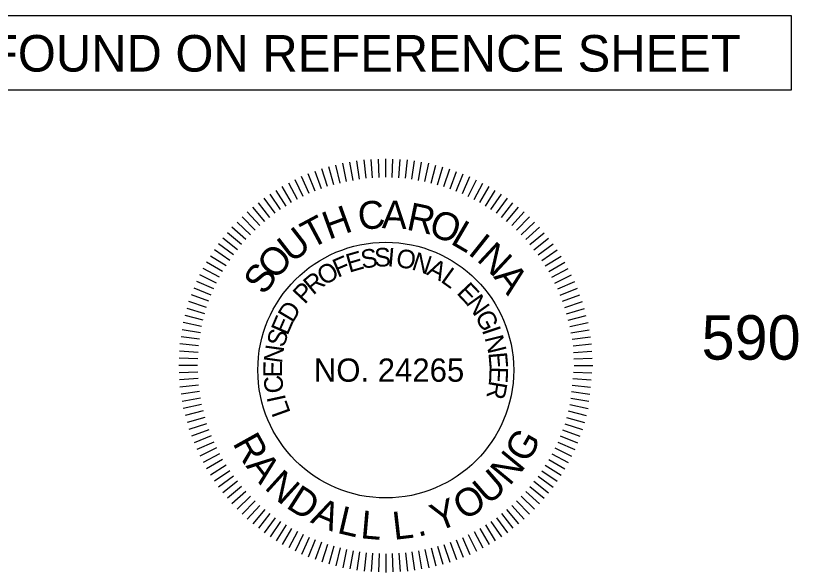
# Model space of a CAD drawing. Extents: x 1964377 to 1966966, y 1116414 to 1123213.
# Drawn here: x 1966800.1 to 1966949.9, y 1117986.1 to 1118092.7 of the extents above; entities that cross this region are included whole.
import ezdxf

# ---------------------------------------------------------------- set-up
doc = ezdxf.new("R2010")
doc.units = 0
for name, color, linetype in [('RD_DDB_Profile_Elev', 7, 'Continuous'), ('RD_Sketch1', 7, 'Continuous'), ('RD_TX_PEShield', 7, 'Continuous')]:
    doc.layers.add(name, color=color, linetype=linetype)

msp = doc.modelspace()

# ---------------------------------------------------------------- linework, layer by layer
at = {"layer": 'RD_Sketch1'}
msp.add_lwpolyline([(1966648.09, 1118092.67), (1966948.51, 1118092.67), (1966948.51, 1118078.41), (1966648.09, 1118078.41)], close=True, dxfattribs=at)
at = {"layer": 'RD_TX_PEShield'}
for p, q in [((1966865.89, 1118061.33), (1966865.39, 1118064.85)), ((1966865.89, 1118061.33), (1966865.39, 1118064.85)), ((1966867.13, 1118061.52), (1966866.76, 1118065.06)), ((1966867.13, 1118061.52), (1966866.76, 1118065.06)), ((1966868.39, 1118061.59), (1966868.14, 1118065.14)), ((1966868.39, 1118061.59), (1966868.14, 1118065.14)), ((1966869.64, 1118061.65), (1966869.52, 1118065.21)), ((1966869.64, 1118061.65), (1966869.52, 1118065.21)), ((1966870.9, 1118061.72), (1966870.9, 1118065.28)), ((1966870.9, 1118061.72), (1966870.9, 1118065.28)), ((1966872.15, 1118061.65), (1966872.28, 1118065.21)), ((1966872.15, 1118061.65), (1966872.28, 1118065.21)), ((1966873.41, 1118061.59), (1966873.66, 1118065.14)), ((1966873.41, 1118061.59), (1966873.66, 1118065.14)), ((1966874.67, 1118061.52), (1966875.04, 1118065.06)), ((1966874.67, 1118061.52), (1966875.04, 1118065.06)), ((1966875.91, 1118061.33), (1966876.4, 1118064.85)), ((1966875.91, 1118061.33), (1966876.4, 1118064.85)), ((1966859.76, 1118059.96), (1966858.66, 1118063.34)), ((1966859.76, 1118059.96), (1966858.66, 1118063.34)), ((1966860.98, 1118060.28), (1966860, 1118063.7)), ((1966860.98, 1118060.28), (1966860, 1118063.7)), ((1966862.19, 1118060.61), (1966861.33, 1118064.06)), ((1966862.19, 1118060.61), (1966861.33, 1118064.06)), ((1966863.4, 1118060.93), (1966862.66, 1118064.41)), ((1966863.4, 1118060.93), (1966862.66, 1118064.41)), ((1966864.65, 1118061.13), (1966864.03, 1118064.63)), ((1966864.65, 1118061.13), (1966864.03, 1118064.63)), ((1966877.15, 1118061.13), (1966877.77, 1118064.63)), ((1966877.15, 1118061.13), (1966877.77, 1118064.63)), ((1966878.39, 1118060.93), (1966879.13, 1118064.41)), ((1966878.39, 1118060.93), (1966879.13, 1118064.41)), ((1966878.39, 1118060.93), (1966879.13, 1118064.41)), ((1966879.61, 1118060.61), (1966880.47, 1118064.06)), ((1966879.61, 1118060.61), (1966880.47, 1118064.06)), ((1966879.61, 1118060.61), (1966880.47, 1118064.06)), ((1966880.82, 1118060.28), (1966881.8, 1118063.7)), ((1966880.82, 1118060.28), (1966881.8, 1118063.7)), ((1966880.82, 1118060.28), (1966881.8, 1118063.7)), ((1966882.04, 1118059.96), (1966883.14, 1118063.34)), ((1966882.04, 1118059.96), (1966883.14, 1118063.34)), ((1966882.04, 1118059.96), (1966883.14, 1118063.34)), ((1966856.24, 1118058.6), (1966854.79, 1118061.86)), ((1966856.24, 1118058.6), (1966854.79, 1118061.86)), ((1966857.41, 1118059.06), (1966856.08, 1118062.35)), ((1966857.41, 1118059.06), (1966856.08, 1118062.35)), ((1966858.59, 1118059.51), (1966857.37, 1118062.85)), ((1966858.59, 1118059.51), (1966857.37, 1118062.85)), ((1966883.21, 1118059.51), (1966884.43, 1118062.85)), ((1966883.21, 1118059.51), (1966884.43, 1118062.85)), ((1966883.21, 1118059.51), (1966884.43, 1118062.85)), ((1966884.38, 1118059.06), (1966885.72, 1118062.35)), ((1966884.38, 1118059.06), (1966885.72, 1118062.35)), ((1966884.38, 1118059.06), (1966885.72, 1118062.35)), ((1966885.56, 1118058.6), (1966887.01, 1118061.86)), ((1966885.56, 1118058.6), (1966887.01, 1118061.86)), ((1966885.56, 1118058.6), (1966887.01, 1118061.86)), ((1966854, 1118057.46), (1966852.33, 1118060.6)), ((1966854, 1118057.46), (1966852.33, 1118060.6)), ((1966855.12, 1118058.03), (1966853.56, 1118061.23)), ((1966855.12, 1118058.03), (1966853.56, 1118061.23)), ((1966886.68, 1118058.03), (1966888.24, 1118061.23)), ((1966886.68, 1118058.03), (1966888.24, 1118061.23)), ((1966886.68, 1118058.03), (1966888.24, 1118061.23)), ((1966887.8, 1118057.46), (1966889.47, 1118060.6)), ((1966887.8, 1118057.46), (1966889.47, 1118060.6)), ((1966887.8, 1118057.46), (1966889.47, 1118060.6)), ((1966851.82, 1118056.21), (1966849.94, 1118059.22)), ((1966851.82, 1118056.21), (1966849.94, 1118059.22)), ((1966852.88, 1118056.89), (1966851.1, 1118059.97)), ((1966852.88, 1118056.89), (1966851.1, 1118059.97)), ((1966888.92, 1118056.89), (1966890.7, 1118059.97)), ((1966888.92, 1118056.89), (1966890.7, 1118059.97)), ((1966888.92, 1118056.89), (1966890.7, 1118059.97)), ((1966889.98, 1118056.21), (1966891.86, 1118059.22)), ((1966889.98, 1118056.21), (1966891.86, 1118059.22)), ((1966889.98, 1118056.21), (1966891.86, 1118059.22)), ((1966849.71, 1118054.84), (1966847.62, 1118057.72)), ((1966849.71, 1118054.84), (1966847.62, 1118057.72)), ((1966850.77, 1118055.52), (1966848.78, 1118058.47)), ((1966850.77, 1118055.52), (1966848.78, 1118058.47)), ((1966891.03, 1118055.52), (1966893.02, 1118058.47)), ((1966891.03, 1118055.52), (1966893.02, 1118058.47)), ((1966891.03, 1118055.52), (1966893.02, 1118058.47)), ((1966892.09, 1118054.84), (1966894.18, 1118057.72)), ((1966892.09, 1118054.84), (1966894.18, 1118057.72)), ((1966892.09, 1118054.84), (1966894.18, 1118057.72)), ((1966847.76, 1118053.25), (1966845.47, 1118055.98)), ((1966847.76, 1118053.25), (1966845.47, 1118055.98)), ((1966848.73, 1118054.04), (1966846.54, 1118056.85)), ((1966848.73, 1118054.04), (1966846.54, 1118056.85)), ((1966893.06, 1118054.04), (1966895.25, 1118056.85)), ((1966893.06, 1118054.04), (1966895.25, 1118056.85)), ((1966893.06, 1118054.04), (1966895.25, 1118056.85)), ((1966894.04, 1118053.25), (1966896.33, 1118055.98)), ((1966894.04, 1118053.25), (1966896.33, 1118055.98)), ((1966894.04, 1118053.25), (1966896.33, 1118055.98)), ((1966846.78, 1118052.46), (1966844.4, 1118055.11)), ((1966846.78, 1118052.46), (1966844.4, 1118055.11)), ((1966895.02, 1118052.46), (1966897.4, 1118055.11)), ((1966895.02, 1118052.46), (1966897.4, 1118055.11)), ((1966895.02, 1118052.46), (1966897.4, 1118055.11)), ((1966845, 1118050.68), (1966842.44, 1118053.15)), ((1966845, 1118050.68), (1966842.44, 1118053.15)), ((1966845.89, 1118051.57), (1966843.42, 1118054.13)), ((1966845.89, 1118051.57), (1966843.42, 1118054.13)), ((1966895.91, 1118051.57), (1966898.38, 1118054.13)), ((1966895.91, 1118051.57), (1966898.38, 1118054.13)), ((1966895.91, 1118051.57), (1966898.38, 1118054.13)), ((1966896.8, 1118050.68), (1966899.35, 1118053.15)), ((1966896.8, 1118050.68), (1966899.35, 1118053.15)), ((1966896.8, 1118050.68), (1966899.35, 1118053.15)), ((1966844.11, 1118049.79), (1966841.47, 1118052.18)), ((1966844.11, 1118049.79), (1966841.47, 1118052.18)), ((1966897.69, 1118049.79), (1966900.33, 1118052.18)), ((1966897.69, 1118049.79), (1966900.33, 1118052.18)), ((1966897.69, 1118049.79), (1966900.33, 1118052.18)), ((1966842.53, 1118047.84), (1966839.73, 1118050.03)), ((1966842.53, 1118047.84), (1966839.73, 1118050.03)), ((1966843.32, 1118048.82), (1966840.6, 1118051.1)), ((1966843.32, 1118048.82), (1966840.6, 1118051.1)), ((1966898.48, 1118048.82), (1966901.2, 1118051.1)), ((1966898.48, 1118048.82), (1966901.2, 1118051.1)), ((1966898.48, 1118048.82), (1966901.2, 1118051.1)), ((1966899.27, 1118047.84), (1966902.07, 1118050.03)), ((1966899.27, 1118047.84), (1966902.07, 1118050.03)), ((1966899.27, 1118047.84), (1966902.07, 1118050.03)), ((1966841.74, 1118046.86), (1966838.86, 1118048.95)), ((1966841.74, 1118046.86), (1966838.86, 1118048.95)), ((1966900.06, 1118046.86), (1966902.94, 1118048.95)), ((1966900.06, 1118046.86), (1966902.94, 1118048.95)), ((1966900.06, 1118046.86), (1966902.94, 1118048.95)), ((1966841.05, 1118045.81), (1966838.1, 1118047.8)), ((1966841.05, 1118045.81), (1966838.1, 1118047.8)), ((1966900.74, 1118045.81), (1966903.69, 1118047.8)), ((1966900.74, 1118045.81), (1966903.69, 1118047.8)), ((1966900.74, 1118045.81), (1966903.69, 1118047.8)), ((1966839.68, 1118043.7), (1966836.6, 1118045.48)), ((1966839.68, 1118043.7), (1966836.6, 1118045.48)), ((1966840.37, 1118044.75), (1966837.35, 1118046.64)), ((1966840.37, 1118044.75), (1966837.35, 1118046.64)), ((1966901.43, 1118044.75), (1966904.44, 1118046.64)), ((1966901.43, 1118044.75), (1966904.44, 1118046.64)), ((1966901.43, 1118044.75), (1966904.44, 1118046.64)), ((1966902.11, 1118043.7), (1966905.2, 1118045.48)), ((1966902.11, 1118043.7), (1966905.2, 1118045.48)), ((1966902.11, 1118043.7), (1966905.2, 1118045.48)), ((1966839.11, 1118042.58), (1966835.97, 1118044.25)), ((1966839.11, 1118042.58), (1966835.97, 1118044.25)), ((1966902.69, 1118042.58), (1966905.83, 1118044.25)), ((1966902.69, 1118042.58), (1966905.83, 1118044.25)), ((1966902.69, 1118042.58), (1966905.83, 1118044.25)), ((1966838.54, 1118041.46), (1966835.35, 1118043.02)), ((1966838.54, 1118041.46), (1966835.35, 1118043.02)), ((1966903.26, 1118041.46), (1966906.45, 1118043.02)), ((1966903.26, 1118041.46), (1966906.45, 1118043.02)), ((1966903.26, 1118041.46), (1966906.45, 1118043.02)), ((1966837.97, 1118040.34), (1966834.72, 1118041.78)), ((1966837.97, 1118040.34), (1966834.72, 1118041.78)), ((1966903.83, 1118040.34), (1966907.08, 1118041.78)), ((1966903.83, 1118040.34), (1966907.08, 1118041.78)), ((1966903.83, 1118040.34), (1966907.08, 1118041.78)), ((1966837.52, 1118039.16), (1966834.22, 1118040.49)), ((1966837.52, 1118039.16), (1966834.22, 1118040.49)), ((1966904.28, 1118039.16), (1966907.57, 1118040.49)), ((1966904.28, 1118039.16), (1966907.57, 1118040.49)), ((1966904.28, 1118039.16), (1966907.57, 1118040.49)), ((1966836.62, 1118036.81), (1966833.23, 1118037.91)), ((1966836.62, 1118036.81), (1966833.23, 1118037.91)), ((1966837.07, 1118037.99), (1966833.73, 1118039.2)), ((1966837.07, 1118037.99), (1966833.73, 1118039.2)), ((1966904.73, 1118037.99), (1966908.07, 1118039.2)), ((1966904.73, 1118037.99), (1966908.07, 1118039.2)), ((1966904.73, 1118037.99), (1966908.07, 1118039.2)), ((1966905.18, 1118036.81), (1966908.57, 1118037.91)), ((1966905.18, 1118036.81), (1966908.57, 1118037.91)), ((1966905.18, 1118036.81), (1966908.57, 1118037.91)), ((1966836.29, 1118035.6), (1966832.87, 1118036.58)), ((1966836.29, 1118035.6), (1966832.87, 1118036.58)), ((1966905.5, 1118035.6), (1966908.92, 1118036.58)), ((1966905.5, 1118035.6), (1966908.92, 1118036.58)), ((1966905.5, 1118035.6), (1966908.92, 1118036.58)), ((1966835.97, 1118034.38), (1966832.52, 1118035.25)), ((1966835.97, 1118034.38), (1966832.52, 1118035.25)), ((1966905.83, 1118034.38), (1966909.28, 1118035.25)), ((1966905.83, 1118034.38), (1966909.28, 1118035.25)), ((1966905.83, 1118034.38), (1966909.28, 1118035.25)), ((1966835.64, 1118033.17), (1966832.16, 1118033.91)), ((1966835.64, 1118033.17), (1966832.16, 1118033.91)), ((1966906.16, 1118033.17), (1966909.64, 1118033.91)), ((1966906.16, 1118033.17), (1966909.64, 1118033.91)), ((1966906.16, 1118033.17), (1966909.64, 1118033.91)), ((1966835.44, 1118031.93), (1966831.94, 1118032.54)), ((1966835.44, 1118031.93), (1966831.94, 1118032.54)), ((1966906.35, 1118031.93), (1966909.85, 1118032.54)), ((1966906.35, 1118031.93), (1966909.85, 1118032.54)), ((1966906.35, 1118031.93), (1966909.85, 1118032.54)), ((1966835.25, 1118030.69), (1966831.73, 1118031.18)), ((1966835.25, 1118030.69), (1966831.73, 1118031.18)), ((1966906.55, 1118030.69), (1966910.07, 1118031.18)), ((1966906.55, 1118030.69), (1966910.07, 1118031.18)), ((1966906.55, 1118030.69), (1966910.07, 1118031.18)), ((1966835.05, 1118029.44), (1966831.51, 1118029.82)), ((1966835.05, 1118029.44), (1966831.51, 1118029.82)), ((1966906.75, 1118029.44), (1966910.29, 1118029.82)), ((1966906.75, 1118029.44), (1966910.29, 1118029.82)), ((1966906.75, 1118029.44), (1966910.29, 1118029.82)), ((1966834.99, 1118028.19), (1966831.44, 1118028.43)), ((1966834.99, 1118028.19), (1966831.44, 1118028.43)), ((1966906.81, 1118028.19), (1966910.36, 1118028.43)), ((1966906.81, 1118028.19), (1966910.36, 1118028.43)), ((1966906.81, 1118028.19), (1966910.36, 1118028.43)), ((1966834.92, 1118026.93), (1966831.37, 1118027.06)), ((1966834.92, 1118026.93), (1966831.37, 1118027.06)), ((1966906.88, 1118026.93), (1966910.43, 1118027.06)), ((1966906.88, 1118026.93), (1966910.43, 1118027.06)), ((1966906.88, 1118026.93), (1966910.43, 1118027.06)), ((1966834.85, 1118025.68), (1966831.29, 1118025.68)), ((1966834.85, 1118025.68), (1966831.29, 1118025.68)), ((1966834.92, 1118024.42), (1966831.37, 1118024.29)), ((1966834.92, 1118024.42), (1966831.37, 1118024.29)), ((1966906.81, 1118024.42), (1966910.36, 1118024.3)), ((1966906.81, 1118024.42), (1966910.36, 1118024.3)), ((1966906.94, 1118025.68), (1966910.5, 1118025.68)), ((1966906.94, 1118025.68), (1966910.5, 1118025.68)), ((1966906.94, 1118025.68), (1966910.5, 1118025.68)), ((1966834.99, 1118023.16), (1966831.44, 1118022.92)), ((1966834.99, 1118023.16), (1966831.44, 1118022.92)), ((1966906.68, 1118023.17), (1966910.21, 1118022.93)), ((1966906.68, 1118023.17), (1966910.21, 1118022.93)), ((1966835.05, 1118021.91), (1966831.51, 1118021.54)), ((1966835.05, 1118021.91), (1966831.51, 1118021.54)), ((1966906.55, 1118021.93), (1966910.07, 1118021.56)), ((1966906.55, 1118021.93), (1966910.07, 1118021.56)), ((1966835.25, 1118020.67), (1966831.73, 1118020.17)), ((1966835.25, 1118020.67), (1966831.73, 1118020.17)), ((1966906.42, 1118020.68), (1966909.93, 1118020.19)), ((1966906.42, 1118020.68), (1966909.93, 1118020.19)), ((1966835.44, 1118019.42), (1966831.94, 1118018.81)), ((1966835.44, 1118019.42), (1966831.94, 1118018.81)), ((1966906.29, 1118019.44), (1966909.78, 1118018.82)), ((1966906.29, 1118019.44), (1966909.78, 1118018.82)), ((1966835.64, 1118018.18), (1966832.16, 1118017.44)), ((1966835.64, 1118018.18), (1966832.16, 1118017.44)), ((1966835.97, 1118016.97), (1966832.52, 1118016.11)), ((1966835.97, 1118016.97), (1966832.52, 1118016.11)), ((1966905.83, 1118016.97), (1966909.28, 1118016.11)), ((1966905.83, 1118016.97), (1966909.28, 1118016.11)), ((1966906.16, 1118018.18), (1966909.64, 1118017.44)), ((1966906.16, 1118018.18), (1966909.64, 1118017.44)), ((1966836.29, 1118015.75), (1966832.87, 1118014.77)), ((1966836.29, 1118015.75), (1966832.87, 1118014.77)), ((1966905.5, 1118015.75), (1966908.92, 1118014.77)), ((1966905.5, 1118015.75), (1966908.92, 1118014.77)), ((1966836.62, 1118014.54), (1966833.23, 1118013.44)), ((1966905.18, 1118014.54), (1966908.57, 1118013.44)), ((1966905.18, 1118014.54), (1966908.57, 1118013.44)), ((1966837.07, 1118013.36), (1966833.73, 1118012.15)), ((1966837.07, 1118013.36), (1966833.73, 1118012.15)), ((1966904.73, 1118013.36), (1966908.07, 1118012.15)), ((1966904.73, 1118013.36), (1966908.07, 1118012.15)), ((1966837.52, 1118012.19), (1966834.22, 1118010.86)), ((1966837.52, 1118012.19), (1966834.22, 1118010.86)), ((1966837.97, 1118011.01), (1966834.72, 1118009.57)), ((1966837.97, 1118011.01), (1966834.72, 1118009.57)), ((1966903.83, 1118011.01), (1966907.08, 1118009.57)), ((1966903.83, 1118011.01), (1966907.08, 1118009.57)), ((1966904.28, 1118012.19), (1966907.57, 1118010.86)), ((1966904.28, 1118012.19), (1966907.57, 1118010.86)), ((1966838.54, 1118009.89), (1966835.35, 1118008.33)), ((1966838.54, 1118009.89), (1966835.35, 1118008.33)), ((1966903.26, 1118009.89), (1966906.45, 1118008.33)), ((1966903.26, 1118009.89), (1966906.45, 1118008.33)), ((1966839.11, 1118008.77), (1966835.97, 1118007.1)), ((1966839.11, 1118008.77), (1966835.97, 1118007.1)), ((1966902.69, 1118008.77), (1966905.83, 1118007.1)), ((1966902.69, 1118008.77), (1966905.83, 1118007.1)), ((1966839.68, 1118007.65), (1966836.6, 1118005.87)), ((1966839.68, 1118007.65), (1966836.6, 1118005.87)), ((1966840.37, 1118006.6), (1966837.35, 1118004.71)), ((1966840.37, 1118006.6), (1966837.35, 1118004.71)), ((1966901.43, 1118006.6), (1966904.44, 1118004.71)), ((1966901.43, 1118006.6), (1966904.44, 1118004.71)), ((1966902.11, 1118007.65), (1966905.2, 1118005.87)), ((1966902.11, 1118007.65), (1966905.2, 1118005.87)), ((1966841.05, 1118005.54), (1966838.1, 1118003.56)), ((1966841.05, 1118005.54), (1966838.1, 1118003.56)), ((1966900.74, 1118005.54), (1966903.69, 1118003.56)), ((1966900.74, 1118005.54), (1966903.69, 1118003.56)), ((1966841.74, 1118004.49), (1966838.86, 1118002.4)), ((1966841.74, 1118004.49), (1966838.86, 1118002.4)), ((1966842.53, 1118003.51), (1966839.73, 1118001.32)), ((1966842.53, 1118003.51), (1966839.73, 1118001.32)), ((1966899.27, 1118003.51), (1966902.07, 1118001.32)), ((1966899.27, 1118003.51), (1966902.07, 1118001.32)), ((1966900.06, 1118004.49), (1966902.94, 1118002.4)), ((1966900.06, 1118004.49), (1966902.94, 1118002.4)), ((1966843.32, 1118002.53), (1966840.6, 1118000.25)), ((1966843.32, 1118002.53), (1966840.6, 1118000.25)), ((1966898.48, 1118002.53), (1966901.2, 1118000.25)), ((1966898.48, 1118002.53), (1966901.2, 1118000.25)), ((1966844.11, 1118001.56), (1966841.47, 1117999.17)), ((1966844.11, 1118001.56), (1966841.47, 1117999.17)), ((1966845, 1118000.67), (1966842.44, 1117998.2)), ((1966845, 1118000.67), (1966842.44, 1117998.2)), ((1966896.8, 1118000.67), (1966899.35, 1117998.2)), ((1966896.8, 1118000.67), (1966899.35, 1117998.2)), ((1966897.69, 1118001.56), (1966900.33, 1117999.17)), ((1966897.69, 1118001.56), (1966900.33, 1117999.17)), ((1966845.89, 1117999.78), (1966843.42, 1117997.22)), ((1966845.89, 1117999.78), (1966843.42, 1117997.22)), ((1966895.91, 1117999.78), (1966898.38, 1117997.22)), ((1966895.91, 1117999.78), (1966898.38, 1117997.22)), ((1966846.78, 1117998.89), (1966844.4, 1117996.24)), ((1966846.78, 1117998.89), (1966844.4, 1117996.24)), ((1966847.76, 1117998.1), (1966845.47, 1117995.37)), ((1966847.76, 1117998.1), (1966845.47, 1117995.37)), ((1966894.04, 1117998.1), (1966896.33, 1117995.37)), ((1966894.04, 1117998.1), (1966896.33, 1117995.37)), ((1966895.02, 1117998.89), (1966897.4, 1117996.24)), ((1966848.73, 1117997.31), (1966846.54, 1117994.5)), ((1966848.73, 1117997.31), (1966846.54, 1117994.5)), ((1966849.71, 1117996.51), (1966847.62, 1117993.63)), ((1966849.71, 1117996.51), (1966847.62, 1117993.63)), ((1966892.09, 1117996.51), (1966894.18, 1117993.63)), ((1966892.09, 1117996.51), (1966894.18, 1117993.63)), ((1966893.06, 1117997.31), (1966895.25, 1117994.5)), ((1966893.06, 1117997.31), (1966895.25, 1117994.5)), ((1966850.77, 1117995.83), (1966848.78, 1117992.88)), ((1966850.77, 1117995.83), (1966848.78, 1117992.88)), ((1966851.82, 1117995.14), (1966849.94, 1117992.13)), ((1966851.82, 1117995.14), (1966849.94, 1117992.13)), ((1966852.88, 1117994.46), (1966851.1, 1117991.38)), ((1966852.88, 1117994.46), (1966851.1, 1117991.38)), ((1966888.92, 1117994.46), (1966890.7, 1117991.38)), ((1966888.92, 1117994.46), (1966890.7, 1117991.38)), ((1966889.98, 1117995.14), (1966891.86, 1117992.13)), ((1966889.98, 1117995.14), (1966891.86, 1117992.13)), ((1966891.03, 1117995.83), (1966893.02, 1117992.88)), ((1966891.03, 1117995.83), (1966893.02, 1117992.88)), ((1966854, 1117993.89), (1966852.33, 1117990.75)), ((1966854, 1117993.89), (1966852.33, 1117990.75)), ((1966855.12, 1117993.32), (1966853.56, 1117990.12)), ((1966855.12, 1117993.32), (1966853.56, 1117990.12)), ((1966886.68, 1117993.32), (1966888.24, 1117990.12)), ((1966886.68, 1117993.32), (1966888.24, 1117990.12)), ((1966887.8, 1117993.89), (1966889.47, 1117990.75)), ((1966887.8, 1117993.89), (1966889.47, 1117990.75)), ((1966856.24, 1117992.75), (1966854.79, 1117989.49)), ((1966856.24, 1117992.75), (1966854.79, 1117989.49)), ((1966857.41, 1117992.3), (1966856.08, 1117989)), ((1966857.41, 1117992.3), (1966856.08, 1117989)), ((1966858.59, 1117991.85), (1966857.37, 1117988.5)), ((1966858.59, 1117991.85), (1966857.37, 1117988.5)), ((1966883.21, 1117991.85), (1966884.43, 1117988.5)), ((1966883.21, 1117991.85), (1966884.43, 1117988.5)), ((1966884.38, 1117992.3), (1966885.72, 1117989)), ((1966884.38, 1117992.3), (1966885.72, 1117989)), ((1966885.56, 1117992.75), (1966887.01, 1117989.49)), ((1966885.56, 1117992.75), (1966887.01, 1117989.49)), ((1966859.76, 1117991.39), (1966858.66, 1117988.01)), ((1966859.76, 1117991.39), (1966858.66, 1117988.01)), ((1966860.98, 1117991.07), (1966860, 1117987.65)), ((1966860.98, 1117991.07), (1966860, 1117987.65)), ((1966862.19, 1117990.74), (1966861.33, 1117987.29)), ((1966862.19, 1117990.74), (1966861.33, 1117987.29)), ((1966863.4, 1117990.42), (1966862.66, 1117986.94)), ((1966863.4, 1117990.42), (1966862.66, 1117986.94)), ((1966864.65, 1117990.22), (1966864.03, 1117986.72)), ((1966864.65, 1117990.22), (1966864.03, 1117986.72)), ((1966865.89, 1117990.02), (1966865.39, 1117986.5)), ((1966865.89, 1117990.02), (1966865.39, 1117986.5)), ((1966875.91, 1117990.02), (1966876.4, 1117986.5)), ((1966875.91, 1117990.02), (1966876.4, 1117986.5)), ((1966877.15, 1117990.22), (1966877.77, 1117986.72)), ((1966877.15, 1117990.22), (1966877.77, 1117986.72)), ((1966878.39, 1117990.42), (1966879.13, 1117986.94)), ((1966878.39, 1117990.42), (1966879.13, 1117986.94)), ((1966879.61, 1117990.74), (1966880.47, 1117987.29)), ((1966879.61, 1117990.74), (1966880.47, 1117987.29)), ((1966880.82, 1117991.07), (1966881.8, 1117987.65)), ((1966880.82, 1117991.07), (1966881.8, 1117987.65)), ((1966882.04, 1117991.39), (1966883.14, 1117988.01)), ((1966882.04, 1117991.39), (1966883.14, 1117988.01)), ((1966867.13, 1117989.83), (1966866.76, 1117986.29)), ((1966867.13, 1117989.83), (1966866.76, 1117986.29)), ((1966868.39, 1117989.76), (1966868.14, 1117986.21)), ((1966868.39, 1117989.76), (1966868.14, 1117986.21)), ((1966869.64, 1117989.7), (1966869.52, 1117986.14)), ((1966869.64, 1117989.7), (1966869.52, 1117986.14)), ((1966870.9, 1117989.63), (1966870.9, 1117986.07)), ((1966870.9, 1117989.63), (1966870.9, 1117986.07)), ((1966872.15, 1117989.7), (1966872.28, 1117986.14)), ((1966872.15, 1117989.7), (1966872.28, 1117986.14)), ((1966873.41, 1117989.76), (1966873.66, 1117986.21)), ((1966873.41, 1117989.76), (1966873.66, 1117986.21)), ((1966874.67, 1117989.83), (1966875.04, 1117986.29)), ((1966874.67, 1117989.83), (1966875.04, 1117986.29))]:
    msp.add_line(p, q, dxfattribs=at)
msp.add_circle((1966870.9, 1118024.8), 24.48, dxfattribs=at)

# ---------------------------------------------------------------- texts
at = {"layer": 'RD_DDB_Profile_Elev'}
msp.add_text('590', height=8.5, dxfattribs=at).set_placement((1966931.34, 1118026.8))
at = {"layer": 'RD_Sketch1'}
msp.add_text('ALIGNMENT CONTROL CAN BE FOUND ON REFERENCE SHEET', height=7, dxfattribs=at).set_placement((1966651.74, 1118081.96))
at = {"layer": 'RD_TX_PEShield'}
for s, height, rotation, p in [('C', 5.34, 6.8832, (1966865.89, 1118051.54)), ('H', 5.34, 19.9102, (1966859.99, 1118049.72)), ('A', 5.34, 357.9448, (1966870.11, 1118051.99)), ('R', 5.34, 348.267, (1966874.69, 1118051.73)), ('T', 5.34, 28.0947, (1966856.56, 1118047.91)), ('O', 5.34, 339.3286, (1966878.83, 1118050.82)), ('L', 5.34, 329.6507, (1966883.09, 1118049.11)), ('U', 5.34, 37.7726, (1966852.88, 1118045.17)), ('I', 5.34, 321.4663, (1966886.43, 1118047.13)), ('O', 5.34, 47.4504, (1966849.71, 1118041.85)), ('N', 5.34, 317.0007, (1966888.12, 1118045.85)), ('E', 3.56, 16.1843, (1966863.9, 1118043.43)), ('S', 3.56, 8.6909, (1966866.39, 1118044.19)), ('S', 3.56, 1.79, (1966868.75, 1118044.59)), ('I', 3.56, 354.889, (1966871.14, 1118044.7)), ('O', 3.56, 350.4045, (1966872.7, 1118044.62)), ('N', 3.56, 341.7029, (1966875.68, 1118044.12)), ('F', 3.56, 23.0853, (1966861.71, 1118042.45)), ('A', 3.56, 333.0013, (1966878.54, 1118043.18)), ('S', 5.34, 54.9027, (1966847.67, 1118038.96)), ('O', 3.56, 31.7869, (1966859.14, 1118040.86)), ('L', 3.56, 324.2997, (1966881.24, 1118041.81)), ('A', 5.34, 307.3229, (1966891.41, 1118042.66)), ('R', 3.56, 39.8902, (1966857, 1118039.04)), ('P', 3.56, 46.7912, (1966855.38, 1118037.27)), ('E', 3.56, 313.2251, (1966884.31, 1118039.51)), ('N', 3.56, 305.7317, (1966886.12, 1118037.63)), ('D', 3.56, 59.074, (1966853.09, 1118033.68)), ('E', 3.56, 66.5674, (1966852.08, 1118031.29)), ('G', 3.56, 297.0301, (1966887.88, 1118035.18)), ('S', 3.56, 73.4683, (1966851.44, 1118028.98)), ('I', 3.56, 288.3285, (1966889.26, 1118032.49)), ('N', 3.56, 283.8441, (1966889.8, 1118031.03)), ('N', 3.56, 82.17, (1966851.03, 1118025.98)), ('E', 3.56, 275.1424, (1966890.53, 1118028.1)), ('E', 3.56, 89.6633, (1966851.04, 1118023.38)), ('E', 3.56, 267.6491, (1966890.79, 1118025.51)), ('C', 3.56, 97.7667, (1966851.44, 1118020.6)), ('R', 3.56, 260.1557, (1966890.72, 1118022.91)), ('I', 3.56, 102.2511, (1966851.83, 1118019.09)), ('L', 3.56, 109.7445, (1966852.74, 1118016.65)), ('R', 5.34, 299.1493, (1966841.5, 1118010.82)), ('G', 5.34, 60.1113, (1966898.01, 1118006.77)), ('N', 5.34, 50.4335, (1966894.59, 1118002.47)), ('A', 5.34, 308.0877, (1966844.02, 1118006.42)), ('N', 5.34, 317.7655, (1966847.5, 1118002.17)), ('U', 5.34, 40.7556, (1966890.5, 1117998.81)), ('D', 5.34, 327.4433, (1966851.63, 1117998.56)), ('O', 5.34, 31.0778, (1966885.85, 1117995.88)), ('Y', 5.34, 21.4, (1966880.78, 1117993.78)), ('A', 5.34, 337.1212, (1966856.32, 1117995.69)), ('L', 5.34, 346.799, (1966861.42, 1117993.65)), ('L', 5.34, 354.9835, (1966865.95, 1117992.62)), ('L', 5.34, 6.5171, (1966872.48, 1117992.28)), ('.', 5.34, 14.7016, (1966877.09, 1117992.84))]:
    msp.add_text(s, height=height, rotation=rotation, dxfattribs=at).set_placement(p)
msp.add_text('NO. 24265', height=4.45, dxfattribs=at).set_placement((1966857.14, 1118022.57))

doc.saveas('drawing.dxf')
